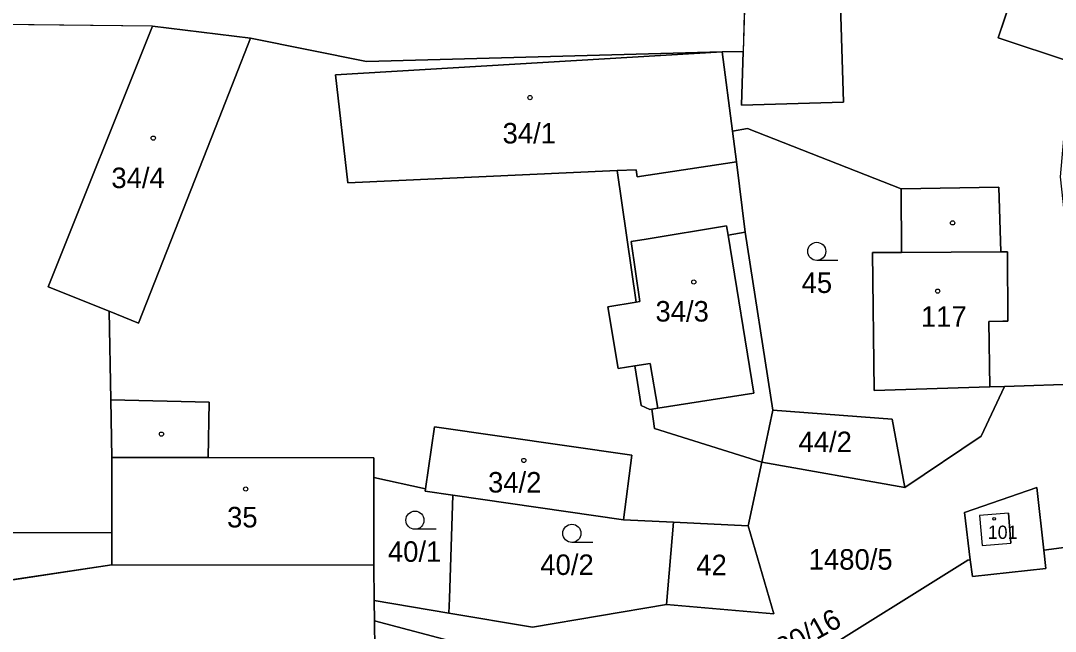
# Model space of a CAD drawing. Extents: x -760642 to -757221, y -1092371 to -1088855.
# Drawn here: x -759363.8 to -759278.1, y -1089791.8 to -1089741.2 of the extents above; entities that cross this region are included whole.
import ezdxf

# ---------------------------------------------------------------- set-up
doc = ezdxf.new("R2010")
doc.units = 0
for name, color, linetype in [('Vrstva 1', 7, 'Continuous'), ('Vrstva 16', 7, 'Continuous'), ('Vrstva 18', 7, 'Continuous'), ('Vrstva 19', 7, 'Continuous'), ('Vrstva 25', 7, 'Continuous'), ('Vrstva 26', 7, 'Continuous'), ('Vrstva 27', 7, 'Continuous'), ('Vrstva 4', 7, 'Continuous')]:
    doc.layers.add(name, color=color, linetype=linetype)

msp = doc.modelspace()

# ---------------------------------------------------------------- linework, layer by layer
at = {"layer": 'Vrstva 1'}
for p, q in [((-759303.6, -1089732.48), (-759303.95, -1089743.71)), ((-759352.89, -1089741.62), (-759384.78, -1089741.25)), ((-759352.89, -1089741.62), (-759361.54, -1089763.21)), ((-759352.89, -1089741.62), (-759344.78, -1089742.6)), ((-759347.36, -1089749.23), (-759344.78, -1089742.6)), ((-759344.78, -1089742.6), (-759335.15, -1089744.56)), ((-759335.15, -1089744.56), (-759305.7, -1089743.76)), ((-759305.7, -1089743.76), (-759303.95, -1089743.71)), ((-759304.85, -1089750.31), (-759305.7, -1089743.76)), ((-759354.04, -1089766.22), (-759347.36, -1089749.23)), ((-759304.85, -1089750.31), (-759303.6, -1089750.09)), ((-759304.52, -1089752.87), (-759304.85, -1089750.31)), ((-759303.6, -1089750.09), (-759290.87, -1089755.11)), ((-759304.52, -1089752.87), (-759312.75, -1089754.11)), ((-759303.78, -1089758.69), (-759304.52, -1089752.87)), ((-759312.83, -1089753.52), (-759314.41, -1089753.59)), ((-759312.82, -1089764.49), (-759314.41, -1089753.59)), ((-759312.75, -1089754.11), (-759312.83, -1089753.52)), ((-759290.87, -1089755.11), (-759290.84, -1089760.37)), ((-759301.49, -1089773.43), (-759303.78, -1089758.69)), ((-759293.24, -1089760.38), (-759290.84, -1089760.37)), ((-759293.12, -1089771.82), (-759293.24, -1089760.38)), ((-759290.84, -1089760.37), (-759282.62, -1089760.32)), ((-759282.62, -1089760.32), (-759282.06, -1089760.32)), ((-759282.06, -1089760.32), (-759282.03, -1089766.06)), ((-759361.54, -1089763.21), (-759356.49, -1089765.24)), ((-759312.82, -1089764.49), (-759315.17, -1089764.89)), ((-759315.17, -1089764.89), (-759314.32, -1089770)), ((-759356.49, -1089765.24), (-759354.04, -1089766.22)), ((-759356.35, -1089772.59), (-759356.49, -1089765.24)), ((-759282.46, -1089766.07), (-759283.62, -1089766.09)), ((-759283.62, -1089766.09), (-759283.53, -1089771.51)), ((-759282.03, -1089766.06), (-759282.46, -1089766.07)), ((-759314.32, -1089770), (-759312.94, -1089769.78)), ((-759312.94, -1089769.78), (-759312.42, -1089773.05)), ((-759283.53, -1089771.51), (-759293.12, -1089771.82)), ((-759284.23, -1089775.61), (-759282.31, -1089771.47)), ((-759283.53, -1089771.51), (-759282.31, -1089771.47)), ((-759282.31, -1089771.47), (-759275.82, -1089771.26)), ((-759356.35, -1089772.59), (-759356.25, -1089777.36)), ((-759312.42, -1089773.05), (-759311.7, -1089773.39)), ((-759311.7, -1089773.39), (-759311.53, -1089773.36)), ((-759311.3, -1089774.96), (-759311.53, -1089773.36)), ((-759301.49, -1089773.43), (-759302.42, -1089777.74)), ((-759301.49, -1089773.43), (-759291.61, -1089774.18)), ((-759290.56, -1089779.84), (-759291.61, -1089774.18)), ((-759329.54, -1089774.82), (-759330.28, -1089779.95)), ((-759329.54, -1089774.82), (-759313.19, -1089777.16)), ((-759302.42, -1089777.74), (-759311.3, -1089774.96)), ((-759290.56, -1089779.84), (-759284.23, -1089775.61)), ((-759356.25, -1089777.36), (-759356.26, -1089783.62)), ((-759348.27, -1089777.37), (-759356.25, -1089777.36)), ((-759334.55, -1089777.38), (-759348.27, -1089777.37)), ((-759334.55, -1089779.02), (-759334.55, -1089777.38)), ((-759313.86, -1089782.52), (-759313.19, -1089777.16)), ((-759302.42, -1089777.74), (-759303.55, -1089783.03)), ((-759290.56, -1089779.84), (-759302.42, -1089777.74)), ((-759334.56, -1089786.28), (-759334.55, -1089779.02)), ((-759334.55, -1089779.02), (-759330.28, -1089779.95)), ((-759330.28, -1089779.95), (-759330.31, -1089780.16)), ((-759330.31, -1089780.16), (-759328.01, -1089780.49)), ((-759279.63, -1089779.86), (-759285.63, -1089781.91)), ((-759279.63, -1089779.86), (-759279.06, -1089785.04)), ((-759328.01, -1089780.49), (-759328.3, -1089789.04)), ((-759328.01, -1089780.49), (-759313.86, -1089782.52)), ((-759285.63, -1089781.91), (-759285.14, -1089785.85)), ((-759313.86, -1089782.52), (-759309.72, -1089782.72)), ((-759310.32, -1089789.54), (-759309.72, -1089782.72)), ((-759309.72, -1089782.72), (-759303.55, -1089783.03)), ((-759356.26, -1089783.62), (-759371.1, -1089783.58)), ((-759356.26, -1089783.62), (-759356.26, -1089786.27)), ((-759303.55, -1089783.03), (-759301.43, -1089790.31)), ((-759267.19, -1089783.47), (-759279.06, -1089785.04)), ((-759279.06, -1089785.04), (-759278.89, -1089786.57)), ((-759389.36, -1089791.2), (-759356.26, -1089786.27)), ((-759334.56, -1089786.28), (-759334.53, -1089789.22)), ((-759285.35, -1089785.88), (-759298.53, -1089794.1)), ((-759285.14, -1089785.85), (-759285.35, -1089785.88)), ((-759285.14, -1089785.85), (-759284.96, -1089787.24)), ((-759284.96, -1089787.24), (-759278.89, -1089786.57)), ((-759328.34, -1089790.26), (-759334.53, -1089789.22)), ((-759334.53, -1089789.22), (-759334.51, -1089790.89)), ((-759328.3, -1089789.04), (-759328.34, -1089790.26)), ((-759310.32, -1089789.54), (-759321.4, -1089791.42)), ((-759301.43, -1089790.31), (-759310.32, -1089789.54)), ((-759321.4, -1089791.42), (-759328.34, -1089790.26)), ((-759334.51, -1089790.89), (-759334.48, -1089793.29)), ((-759320.3, -1089794.67), (-759334.51, -1089790.89))]:
    msp.add_line(p, q, dxfattribs=at)
at = {"layer": 'Vrstva 25'}
for p, q in [((-759296.11, -1089761.03), (-759297.86, -1089761.03)), ((-759329.4, -1089783.31), (-759331.15, -1089783.31)), ((-759316.4, -1089784.4), (-759318.15, -1089784.4))]:
    msp.add_line(p, q, dxfattribs=at)
for centre, radius in [((-759321.62, -1089747.54), 0.175), ((-759352.83, -1089750.9), 0.175), ((-759286.61, -1089757.92), 0.175), ((-759297.86, -1089760.28), 0.75), ((-759308.05, -1089762.82), 0.175), ((-759287.85, -1089763.58), 0.175), ((-759352.15, -1089775.43), 0.175), ((-759322.13, -1089777.61), 0.175), ((-759345.17, -1089779.98), 0.175), ((-759331.15, -1089782.56), 0.75), ((-759318.15, -1089783.65), 0.75), ((-759283.16, -1089782.45), 0.117)]:
    msp.add_circle(centre, radius, dxfattribs=at)
at = {"layer": 'Vrstva 26'}
for points in [[(-759296.11, -1089732.77), (-759283.35, -1089731.84), (-759283.81, -1089722.53), (-759303.25, -1089723.2), (-759303.6, -1089732.48), (-759303.95, -1089743.71), (-759304.09, -1089748.18), (-759295.66, -1089747.93), (-759296.11, -1089732.77)], [(-759283.35, -1089731.84), (-759296.11, -1089732.77), (-759295.66, -1089747.93), (-759304.09, -1089748.18), (-759303.95, -1089743.71), (-759305.7, -1089743.76), (-759304.85, -1089750.31), (-759303.6, -1089750.09), (-759290.87, -1089755.11), (-759282.77, -1089754.95), (-759282.62, -1089760.32), (-759282.06, -1089760.32), (-759282.03, -1089766.06), (-759282.46, -1089766.07), (-759283.62, -1089766.09), (-759283.53, -1089771.51), (-759282.31, -1089771.47), (-759275.82, -1089771.26), (-759277.67, -1089754.1), (-759277.17, -1089748.44), (-759276.83, -1089744.58), (-759282.82, -1089742.58), (-759280.01, -1089734.15), (-759283.35, -1089731.84)], [(-759282.82, -1089742.58), (-759276.83, -1089744.58), (-759273.98, -1089736.64), (-759280.01, -1089734.15), (-759282.82, -1089742.58)], [(-759371.1, -1089783.58), (-759356.26, -1089783.62), (-759356.25, -1089777.36), (-759356.35, -1089772.59), (-759356.49, -1089765.24), (-759361.54, -1089763.21), (-759352.89, -1089741.62), (-759384.78, -1089741.25), (-759389.78, -1089758.07), (-759398.69, -1089784.79), (-759388.58, -1089783.67), (-759388.83, -1089778.81), (-759371.1, -1089779.03), (-759371.1, -1089783.58)], [(-759354.04, -1089766.22), (-759347.36, -1089749.23), (-759344.78, -1089742.6), (-759352.89, -1089741.62), (-759361.54, -1089763.21), (-759356.49, -1089765.24), (-759354.04, -1089766.22)], [(-759336.72, -1089754.61), (-759337.74, -1089745.65), (-759305.7, -1089743.76), (-759335.15, -1089744.56), (-759344.78, -1089742.6), (-759347.36, -1089749.23), (-759354.04, -1089766.22), (-759356.49, -1089765.24), (-759356.35, -1089772.59), (-759348.19, -1089772.78), (-759348.27, -1089777.37), (-759334.55, -1089777.38), (-759334.55, -1089779.02), (-759330.28, -1089779.95), (-759329.54, -1089774.82), (-759313.19, -1089777.16), (-759313.86, -1089782.52), (-759309.72, -1089782.72), (-759303.55, -1089783.03), (-759302.42, -1089777.74), (-759311.3, -1089774.96), (-759311.53, -1089773.36), (-759311.7, -1089773.39), (-759312.42, -1089773.05), (-759312.94, -1089769.78), (-759314.32, -1089770), (-759315.17, -1089764.89), (-759312.82, -1089764.49), (-759314.41, -1089753.59), (-759336.72, -1089754.61)], [(-759304.85, -1089750.31), (-759305.7, -1089743.76), (-759337.74, -1089745.65), (-759336.72, -1089754.61), (-759314.41, -1089753.59), (-759312.83, -1089753.52), (-759312.75, -1089754.11), (-759304.52, -1089752.87), (-759304.85, -1089750.31)], [(-759291.61, -1089774.18), (-759290.56, -1089779.84), (-759284.23, -1089775.61), (-759282.31, -1089771.47), (-759283.53, -1089771.51), (-759293.12, -1089771.82), (-759293.24, -1089760.38), (-759290.84, -1089760.37), (-759290.87, -1089755.11), (-759303.6, -1089750.09), (-759304.85, -1089750.31), (-759304.52, -1089752.87), (-759303.78, -1089758.69), (-759301.49, -1089773.43), (-759291.61, -1089774.18)], [(-759305.34, -1089758.17), (-759305.21, -1089758.93), (-759303.78, -1089758.69), (-759304.52, -1089752.87), (-759312.75, -1089754.11), (-759312.83, -1089753.52), (-759314.41, -1089753.59), (-759312.82, -1089764.49), (-759312.52, -1089764.44), (-759313.24, -1089759.47), (-759312, -1089759.27), (-759305.34, -1089758.17)], [(-759282.62, -1089760.32), (-759282.77, -1089754.95), (-759290.87, -1089755.11), (-759290.84, -1089760.37), (-759282.62, -1089760.32)], [(-759315.17, -1089764.89), (-759314.32, -1089770), (-759312.94, -1089769.78), (-759311.66, -1089769.57), (-759311.03, -1089773.28), (-759303.08, -1089772.03), (-759305.21, -1089758.93), (-759305.34, -1089758.17), (-759312, -1089759.27), (-759313.24, -1089759.47), (-759312.52, -1089764.44), (-759312.82, -1089764.49), (-759315.17, -1089764.89)], [(-759303.08, -1089772.03), (-759305.21, -1089758.93), (-759305.34, -1089758.17), (-759312, -1089759.27), (-759313.24, -1089759.47), (-759312.52, -1089764.44), (-759312.82, -1089764.49), (-759315.17, -1089764.89), (-759314.32, -1089770), (-759312.94, -1089769.78), (-759311.66, -1089769.57), (-759311.03, -1089773.28), (-759303.08, -1089772.03)], [(-759305.21, -1089758.93), (-759303.08, -1089772.03), (-759311.03, -1089773.28), (-759311.53, -1089773.36), (-759311.3, -1089774.96), (-759302.42, -1089777.74), (-759301.49, -1089773.43), (-759303.78, -1089758.69), (-759305.21, -1089758.93)], [(-759282.62, -1089760.32), (-759290.84, -1089760.37), (-759293.24, -1089760.38), (-759293.12, -1089771.82), (-759283.53, -1089771.51), (-759283.62, -1089766.09), (-759282.46, -1089766.07), (-759282.03, -1089766.06), (-759282.06, -1089760.32), (-759282.62, -1089760.32)], [(-759311.03, -1089773.28), (-759311.66, -1089769.57), (-759312.94, -1089769.78), (-759312.42, -1089773.05), (-759311.7, -1089773.39), (-759311.53, -1089773.36), (-759311.03, -1089773.28)], [(-759275.82, -1089771.26), (-759282.31, -1089771.47), (-759284.23, -1089775.61), (-759290.56, -1089779.84), (-759302.42, -1089777.74), (-759303.55, -1089783.03), (-759301.43, -1089790.31), (-759310.32, -1089789.54), (-759321.4, -1089791.42), (-759328.34, -1089790.26), (-759334.53, -1089789.22), (-759334.51, -1089790.89), (-759320.3, -1089794.67), (-759333.52, -1089805.77), (-759331.6, -1089808.73), (-759327.52, -1089804.83), (-759317.69, -1089795.45), (-759312.39, -1089793.06), (-759306.421, -1089795.291)], [(-759348.27, -1089777.37), (-759348.19, -1089772.78), (-759356.35, -1089772.59), (-759356.25, -1089777.36), (-759348.27, -1089777.37)], [(-759290.56, -1089779.84), (-759291.61, -1089774.18), (-759301.49, -1089773.43), (-759302.42, -1089777.74), (-759290.56, -1089779.84)], [(-759329.54, -1089774.82), (-759330.28, -1089779.95), (-759330.31, -1089780.16), (-759328.01, -1089780.49), (-759313.86, -1089782.52), (-759313.19, -1089777.16), (-759329.54, -1089774.82)], [(-759348.27, -1089777.37), (-759356.25, -1089777.36), (-759356.26, -1089783.62), (-759356.26, -1089786.27), (-759334.56, -1089786.28), (-759334.55, -1089779.02), (-759334.55, -1089777.38), (-759348.27, -1089777.37)], [(-759334.56, -1089786.28), (-759334.53, -1089789.22), (-759328.34, -1089790.26), (-759328.3, -1089789.04), (-759328.01, -1089780.49), (-759330.31, -1089780.16), (-759330.28, -1089779.95), (-759334.55, -1089779.02), (-759334.56, -1089786.28)], [(-759306.421, -1089795.291), (-759306.13, -1089795.4), (-759305.01, -1089797.64), (-759298.53, -1089794.1), (-759285.35, -1089785.88), (-759285.14, -1089785.85), (-759285.63, -1089781.91), (-759279.63, -1089779.86), (-759279.06, -1089785.04), (-759267.19, -1089783.47)], [(-759278.89, -1089786.57), (-759279.06, -1089785.04), (-759279.63, -1089779.86), (-759285.63, -1089781.91), (-759285.14, -1089785.85), (-759284.96, -1089787.24), (-759278.89, -1089786.57)], [(-759313.86, -1089782.52), (-759328.01, -1089780.49), (-759328.3, -1089789.04), (-759328.34, -1089790.26), (-759321.4, -1089791.42), (-759310.32, -1089789.54), (-759309.72, -1089782.72), (-759313.86, -1089782.52)], [(-759281.78, -1089784.47), (-759281.99, -1089781.98), (-759284.38, -1089782.18), (-759284.17, -1089784.67), (-759281.78, -1089784.47)], [(-759309.72, -1089782.72), (-759310.32, -1089789.54), (-759301.43, -1089790.31), (-759303.55, -1089783.03), (-759309.72, -1089782.72)], [(-759407.21, -1089818.52), (-759399.61, -1089817.98), (-759391.32, -1089815.46), (-759395.22, -1089798.28), (-759387.87, -1089796.49), (-759389.36, -1089791.2), (-759356.26, -1089786.27), (-759356.26, -1089783.62), (-759371.1, -1089783.58), (-759388.58, -1089783.67), (-759398.69, -1089784.79), (-759401.5, -1089785.06), (-759405.97, -1089800.41), (-759407.21, -1089818.52)], [(-759267.19, -1089783.47), (-759279.06, -1089785.04), (-759278.89, -1089786.57), (-759284.96, -1089787.24), (-759285.14, -1089785.85), (-759285.35, -1089785.88), (-759298.53, -1089794.1), (-759305.01, -1089797.64), (-759304.22, -1089799.22), (-759307.286, -1089801.805), (-759313.01, -1089806.63), (-759318.03, -1089808.23), (-759324.93, -1089816.88), (-759328.354, -1089823.185), (-759330.35, -1089826.86), (-759337.76, -1089834.94), (-759338.42, -1089835.66), (-759335.42, -1089839.71), (-759334.06, -1089838.74), (-759323.6, -1089824.23), (-759319.83, -1089819.01), (-759313.859, -1089810.991)], [(-759358.78, -1089800.83), (-759339.09, -1089794.72), (-759334.48, -1089793.29), (-759334.51, -1089790.89), (-759334.53, -1089789.22), (-759334.56, -1089786.28), (-759356.26, -1089786.27), (-759389.36, -1089791.2), (-759387.87, -1089796.49), (-759395.22, -1089798.28), (-759391.32, -1089815.46), (-759383.23, -1089813), (-759385.39, -1089805.3), (-759365.43, -1089801.18), (-759364.91, -1089808.42), (-759360.28, -1089808.83), (-759356.8, -1089808.2), (-759358.78, -1089800.83)], [(-759336.42, -1089801.28), (-759333.52, -1089805.77), (-759320.3, -1089794.67), (-759334.51, -1089790.89), (-759334.48, -1089793.29), (-759339.09, -1089794.72), (-759336.42, -1089801.28)]]:
    msp.add_lwpolyline(points, dxfattribs=at)
at = {"layer": 'Vrstva 27'}
msp.add_lwpolyline([(-759273.69, -1089700.21), (-759288.15, -1089693.62), (-759297.08, -1089688.73), (-759303.27, -1089717.63), (-759303.95, -1089743.71), (-759305.7, -1089743.76), (-759335.15, -1089744.56), (-759344.78, -1089742.6), (-759352.89, -1089741.62), (-759384.78, -1089741.25), (-759398.69, -1089784.79), (-759401.5, -1089785.06), (-759405.97, -1089800.41), (-759407.21, -1089818.52), (-759413.62, -1089821.43), (-759430.4, -1089822.99)], dxfattribs=at)
at = {"layer": 'Vrstva 4'}
for p, q in [((-759296.11, -1089732.77), (-759295.66, -1089747.93)), ((-759280.01, -1089734.15), (-759282.82, -1089742.58)), ((-759276.83, -1089744.58), (-759282.82, -1089742.58)), ((-759337.74, -1089745.65), (-759305.7, -1089743.76)), ((-759303.95, -1089743.71), (-759304.09, -1089748.18)), ((-759336.72, -1089754.61), (-759337.74, -1089745.65)), ((-759304.09, -1089748.18), (-759295.66, -1089747.93)), ((-759314.41, -1089753.59), (-759336.72, -1089754.61)), ((-759290.87, -1089755.11), (-759282.77, -1089754.95)), ((-759282.77, -1089754.95), (-759282.62, -1089760.32)), ((-759305.34, -1089758.17), (-759312, -1089759.27)), ((-759305.21, -1089758.93), (-759305.34, -1089758.17)), ((-759303.78, -1089758.69), (-759305.21, -1089758.93)), ((-759303.08, -1089772.03), (-759305.21, -1089758.93)), ((-759312, -1089759.27), (-759313.24, -1089759.47)), ((-759313.24, -1089759.47), (-759312.52, -1089764.44)), ((-759312.52, -1089764.44), (-759312.82, -1089764.49)), ((-759312.94, -1089769.78), (-759311.66, -1089769.57)), ((-759311.66, -1089769.57), (-759311.03, -1089773.28)), ((-759356.35, -1089772.59), (-759348.19, -1089772.78)), ((-759303.08, -1089772.03), (-759311.03, -1089773.28)), ((-759348.27, -1089777.37), (-759348.19, -1089772.78)), ((-759311.53, -1089773.36), (-759311.03, -1089773.28)), ((-759281.99, -1089781.98), (-759284.38, -1089782.18)), ((-759281.99, -1089781.98), (-759281.78, -1089784.47)), ((-759284.38, -1089782.18), (-759284.17, -1089784.67)), ((-759284.17, -1089784.67), (-759281.78, -1089784.47)), ((-759356.26, -1089786.27), (-759334.56, -1089786.28))]:
    msp.add_line(p, q, dxfattribs=at)

# ---------------------------------------------------------------- texts
at = {"layer": 'Vrstva 16'}
msp.add_text('1480/16', height=1.7, rotation=29.08584, dxfattribs=at).set_placement((-759302.86, -1089795.28))
at = {"layer": 'Vrstva 18'}
for s, p in [('45', (-759299.118, -1089763.73)), ('44/2', (-759299.376, -1089776.92)), ('40/1', (-759333.388, -1089786.01)), ('40/2', (-759320.76, -1089787.1)), ('42', (-759307.841, -1089787.12)), ('1480/5', (-759298.53, -1089786.66))]:
    msp.add_text(s, height=1.7, dxfattribs=at).set_placement(p)
at = {"layer": 'Vrstva 19'}
for s, height, p in [('34/1', 1.7, (-759323.89, -1089751.34)), ('34/4', 1.7, (-759356.298, -1089755.04)), ('34/3', 1.7, (-759311.224, -1089766.1)), ('117', 1.7, (-759289.234, -1089766.53)), ('34/2', 1.7, (-759325.092, -1089780.27)), ('35', 1.7, (-759346.714, -1089783.16)), ('101', 1.1, (-759283.692, -1089784.11))]:
    msp.add_text(s, height=height, dxfattribs=at).set_placement(p)

doc.saveas('drawing.dxf')
